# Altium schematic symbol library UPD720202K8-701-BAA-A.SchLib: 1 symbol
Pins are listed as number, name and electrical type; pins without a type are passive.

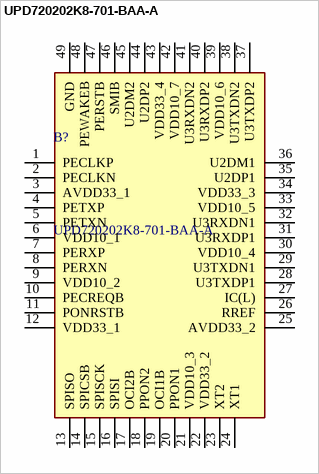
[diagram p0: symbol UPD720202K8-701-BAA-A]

## UPD720202K8-701-BAA-A
designator B?
PD720202 is a USB host controller LSI compatible with the USB 3.0 and xHCI (eXtensible Host Controller Interface) 1.0 specifications. The system bus is compatible with the PCIe Gen2 specification. The controller provides two USB ports with LS (Low-Speed) / FS (Full-Speed) / HS (High-Speed) / SS (SuperSpeed) support.PD720202 comes in a 48-pin QFN package and has the following improvements over previous products.	Reduced power consumption in low-power mode to 4.5mW, a reduction of 90% compared with Renesas; Manufacturer_Name: Renesas Electronics; Geometry.Height: 0.9mm
footprint QFN50P700X700X90-49N-D
pins: 1 PECLKP, 2 PECLKN, 3 AVDD33_1, 4 PETXP, 5 PETXN, 6 VDD10_1, 7 PERXP, 8 PERXN, 9 VDD10_2, 10 PECREQB, 11 PONRSTB, 12 VDD33_1, 13 SPISO, 14 SPICSB, 15 SPISCK, 16 SPISI, 17 OCI2B, 18 PPON2, 19 OCI1B, 20 PPON1, 21 VDD10_3, 22 VDD33_2, 23 XT2, 24 XT1, 25 AVDD33_2, 26 RREF, 27 IC(L), 28 U3TXDP1, 29 U3TXDN1, 30 VDD10_4, 31 U3RXDP1, 32 U3RXDN1, 33 VDD10_5, 34 VDD33_3, 35 U2DP1, 36 U2DM1, 37 U3TXDP2, 38 U3TXDN2, 39 VDD10_6, 40 U3RXDP2, 41 U3RXDN2, 42 VDD10_7, 43 VDD33_4, 44 U2DP2, 45 U2DM2, 46 SMIB, 47 PERSTB, 48 PEWAKEB, 49 GND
